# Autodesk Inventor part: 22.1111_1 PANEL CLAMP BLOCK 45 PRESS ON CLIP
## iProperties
Created: 2008-12
Part Number: 22.1111_1 PANEL CLAMP BLOCK 45 PRESS ON CLIP
Document SubType Name: Modeling
Designer: Administrator
Density: 1.06 g/cm^3
Material: ABS Plastic
Mass: 8.15832 g
Surface Area: 31.3355 cm^2
Volume: 7.69653 cm^3
Author: Administrator
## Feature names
1. Base1
